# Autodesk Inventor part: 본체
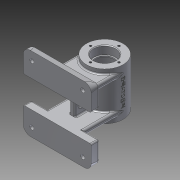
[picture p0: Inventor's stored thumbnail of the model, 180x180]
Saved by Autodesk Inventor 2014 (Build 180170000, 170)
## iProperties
Created: 2016-07
Part Number: 본체
Material: Aluminum 6061
Document SubType Name: Modeling
Designer: user
Density: 2.71 g/cm^3
Appearance: Aluminum - Flat
Mass: 507.574 g
Surface Area: 543.645 cm^2
Volume: 187.297 cm^3
Author: user
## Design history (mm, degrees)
sketch "Sketch1"
  geometry: C1 r 27 at (0, 0); 1 further point
  constraints: 1 centre point, 1 coincident
  dimensions: "d0" = 54 diameter of C1
extrude "Extrusion1" new body sketch "Sketch1" stored distance "d1" = 70; taper "d2" = 0 deg
workplane "Work Plane1"
sketch "Sketch2"
  geometry: L1 (27, -35)-(27, 35) reference; L2 (27, 35)-(-27, 35) reference; L3 (-27, -35)-(-27, 35) reference; L4 (-27, -35)-(27, -35) reference; L5 (0, 55)-(50, 55); L6 (50, 55)-(50, 20); L7 (50, 20)-(0, 20); L8 (-50, 20)-(0, 20); L9 (-50, 55)-(-50, 20); L10 (0, 55)-(-50, 55); 1 further point
  constraints: 12 end point, 1 perpendicular
  dimensions: "d5" = 50 distance of L5.start L5.end; "d6" = 35 distance of L5.end L6.end; "d7" = 50 distance of L6.end L7.end; "d8" = 90 deg angle of L6 L5; "d9" = 90 deg angle of L7 L6; "d10" = 55 distance from line of L4 L6.end; "d12" = 23 distance from line of L1 L6.end; "d13" = 50 distance of L5.start L9.start; "d14" = 50 distance of L8.start L7.end; "d15" = 35 distance of L9.start L8.start; "d16" = 23 distance from line of L3 L9.start
extrude "Extrusion2" join sketch "Sketch2" distance "d17" = 12; taper "d18" = 0 deg
mirror "Mirror1"
sketch "Sketch3"
  geometry: L1 (50, -20)-(-50, -20) reference; L2 (-27, -28)-(27, -28); L3 (27, -28)-(27, -20); L4 (27, -20)-(-27, -20); L5 (-27, -20)-(-27, -28); 3 further points
  constraints: 8 end point, 3 midpoint, 2 parallel, 1 horizontal, 1 perpendicular, 1 vertical alignment
  dimensions: "d19" = 54 distance of L4.end L3.end; "d20" = 8 distance of L3.end L2.end
extrude "Extrusion3" join sketch "Sketch3" stored distance "d21" = 12; taper "d22" = 0 deg
mirror "Mirror2"
workplane "Work Plane2"
sketch "Sketch4"
  geometry: L1 (4, 20)-(-4, 20); L2 (-4, 20)-(-4, -20); L3 (-4, -20)-(4, -20); L4 (4, -20)-(4, 20); 3 further points
  constraints: 8 end point, 2 midpoint, 2 parallel, 1 horizontal, 1 horizontal alignment, 1 perpendicular, 1 vertical alignment
  dimensions: "d24" = 8 distance of L3.end L2.end; "d25" = 40 distance of L2.end L1.end
extrude "Extrusion4" join sketch "Sketch4" stored distance "d26" = 10; taper "d27" = 0 deg
sketch "Sketch5"
  geometry: L1 (0, 0)-(0, 21.298) reference; L2 (40, 21.298)-(40, 0) reference; L3 (12, 13.5)-(28, 13.5); L4 (12, 6.5)-(28, 6.5); L5 (40, -22)-(75, -22) reference; A1 r 3.5 centre (12, 10) between (12, 13.5) and (12, 6.5); A2 r 3.5 centre (28, 10) between (28, 6.5) and (28, 13.5); 1 further point
  constraints: 4 end point, 4 point on circle, 2 centre point, 2 tangent
  dimensions: "d29" = 7 diameter of A1; "d30" = 7 diameter of A2; "d31" = 23 dimension on A2 A1; "d32" = 12 distance from line of L2 A2.centre; "d34" = 12 distance from line of L1 A1.centre; "d35" = 16 distance of L3.start L3.end; "d36" = 16 distance of L4.start L4.end; "d114" = 32 distance from line of L5 A2.centre
extrude "Extrusion5" cut sketch "Sketch5" stored distance "d37" = 10; taper "d38" = 0 deg
sketch "Sketch6"
  geometry: L1 (-50, -20)-(-50, -55) reference; L2 (-50, -55)-(50, -55) reference; 2 further points
  dimensions: "d39" = 12.5 distance from line of point (-37.5, -42.5) L1; "d40" = 12.5 distance from line of point (-37.5, -42.5) L2
hole "Hole1" sketch "Sketch6" at (-37.5, -42.5) diameter "d41" = 6; stored, may be unused: countersink angle "d45" = 90 deg, drill point angle "d47" = 0 deg; dims "d42" = 6, "d43" = 10, "d44" = 4, "d46" = 12
mirror "Mirror3"
mirror "Mirror4"
sketch "Sketch7"
  geometry: C1 r 27 at (0, 0) reference; C2 r 16 at (0, 0)
  constraints: 1 centre point, 1 coincident
  dimensions: "d48" = 32 diameter of C2
extrude "Extrusion6" cut sketch "Sketch7" distance "d49" = 12; taper "d50" = 0 deg
sketch "Sketch8"
  geometry: C1 r 16 at (0, 0) reference; C2 r 14 at (0, 0)
  constraints: 1 centre point, 1 coincident
  dimensions: "d51" = 28 diameter of C2
extrude "Extrusion7" cut sketch "Sketch8" distance "d52" = 2; taper "d53" = 0 deg
sketch "Sketch9"
  geometry: C1 r 14 at (0, 0) reference; C2 r 22 at (0, 0)
  constraints: 1 centre point, 1 coincident
  dimensions: "d54" = 44 diameter of C2
extrude "Extrusion8" cut sketch "Sketch9" distance "d55" = 42; taper "d56" = 0 deg
mirror "Mirror5"
sketch "Sketch10"
  geometry: C1 r 16 at (0, 0) reference; 1 further point
  dimensions: "d57" = 21 distance of C1.centre point (0, 21)
hole "Hole2" sketch "Sketch10" at (0, 21) diameter "d58" = 3.242; stored, may be unused: countersink angle "d62" = 90 deg, drill point angle "d64" = 118 deg; dims "d59" = 8, "d60" = 10, "d61" = 4, "d63" = 10
pattern_circular "Circular Pattern1" dims angle "d66" = 360 deg
mirror "Mirror6"
workplane "Work Plane3"
sketch "Sketch11"
  geometry: L1 (27, 35)-(-27, 35) reference; L2 (27, -35)-(27, 35) reference; L3 (-20.368, 20.739)-(-20.368, -20.739); L4 (-20.368, -20.739)-(20.368, -20.739); L5 (20.368, -20.739)-(20.368, 20.739); L6 (20.368, 20.739)-(-20.368, 20.739); 4 further points
  constraints: 2 midpoint, 1 horizontal alignment, 1 vertical alignment, 2 other
  dimensions: "d69" = 35 distance from line of L1 point (0, 0); "d70" = 27 distance from line of point (0, 0) L2
emboss "Emboss1" sketch "Sketch11" dims "d71" = 0.5, "d72" = 0
workplane "Work Plane4"
sketch "Sketch12"
  geometry: L1 (27, 35)-(-27, 35) reference; C1 r 5 at (0, 13); 1 further point
  constraints: 1 centre point
  dimensions: "d75" = 10 diameter of C1; "d76" = 22 distance from line of L1 C1.centre
extrude "Extrusion9" join sketch "Sketch12" stored distance "d77" = 42; taper "d78" = 0 deg
sketch "Sketch13"
  geometry: C1 r 5 at (0, 0) reference; 2 further points
  constraints: 1 coincident
hole "Hole3" sketch "Sketch13" at (0, 0) diameter "d79" = 5.188; stored, may be unused: countersink angle "d83" = 90 deg, drill point angle "d85" = 0 deg; dims "d80" = 9, "d81" = 10, "d82" = 4, "d84" = 9
sketch "Sketch14"
  geometry: L1 (0, 0)-(0, -81.093); L2 (0, 0)-(-15.898, -25.441)
  constraints: 4 end point, 1 vertical
  dimensions: "d86" = 32 deg angle of L2 L1; "d87" = 30 distance of L1.start L2.end
workplane "Work Plane5"
sketch "Sketch15"
  geometry: C1 r 6 at (0, 0); 1 further point
  constraints: 1 centre point, 1 coincident
  dimensions: "d88" = 12 diameter of C1
extrude "Extrusion10" join sketch "Sketch15" stored distance "d89" = 42; taper "d90" = 0 deg
sketch "Sketch16"
  geometry: C1 r 6 at (0, 0) reference; 1 further point
  constraints: 1 coincident
hole "Hole4" sketch "Sketch16" at (0, 0) diameter "d91" = 5.188; stored, may be unused: countersink angle "d95" = 90 deg, drill point angle "d97" = 0 deg; dims "d92" = 9, "d93" = 10, "d94" = 4, "d96" = 9
fillet "Fillet3" dims "d102" = 2
fillet "Fillet4" dims "d103" = 2
fillet "Fillet5" dims "d104" = 3
fillet "Fillet6" dims "d105" = 2
fillet "Fillet8" dims "d107" = 2
fillet "Fillet9" dims "d108" = 2
chamfer "Chamfer1" distance "d109" = 1; stored, may be unused: second distance "d110" = 2, angle "d111" = 45 deg
fillet "Fillet10" dims "d112" = 0.3
fillet "Fillet11" dims "d113" = 3
feature "FaceDraft3" dims angle "d115" = -20 deg
feature "FaceDraft5" dims angle "d121" = -20 deg
fillet "Fillet15" dims "d122" = 10, "d123" = 5
mirror "Mirror9"
mirror "Mirror10"
fillet "Fillet16" dims "d124" = 2
body "Solid1"
other parameters: "d23" = -48, "d68" = 27
